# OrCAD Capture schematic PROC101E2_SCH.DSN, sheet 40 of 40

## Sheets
40 18. ICSSG RGMII_1 ETHERNET PHY: size C; title: ICSSG2 RGMII_1 ETHERNET PHY
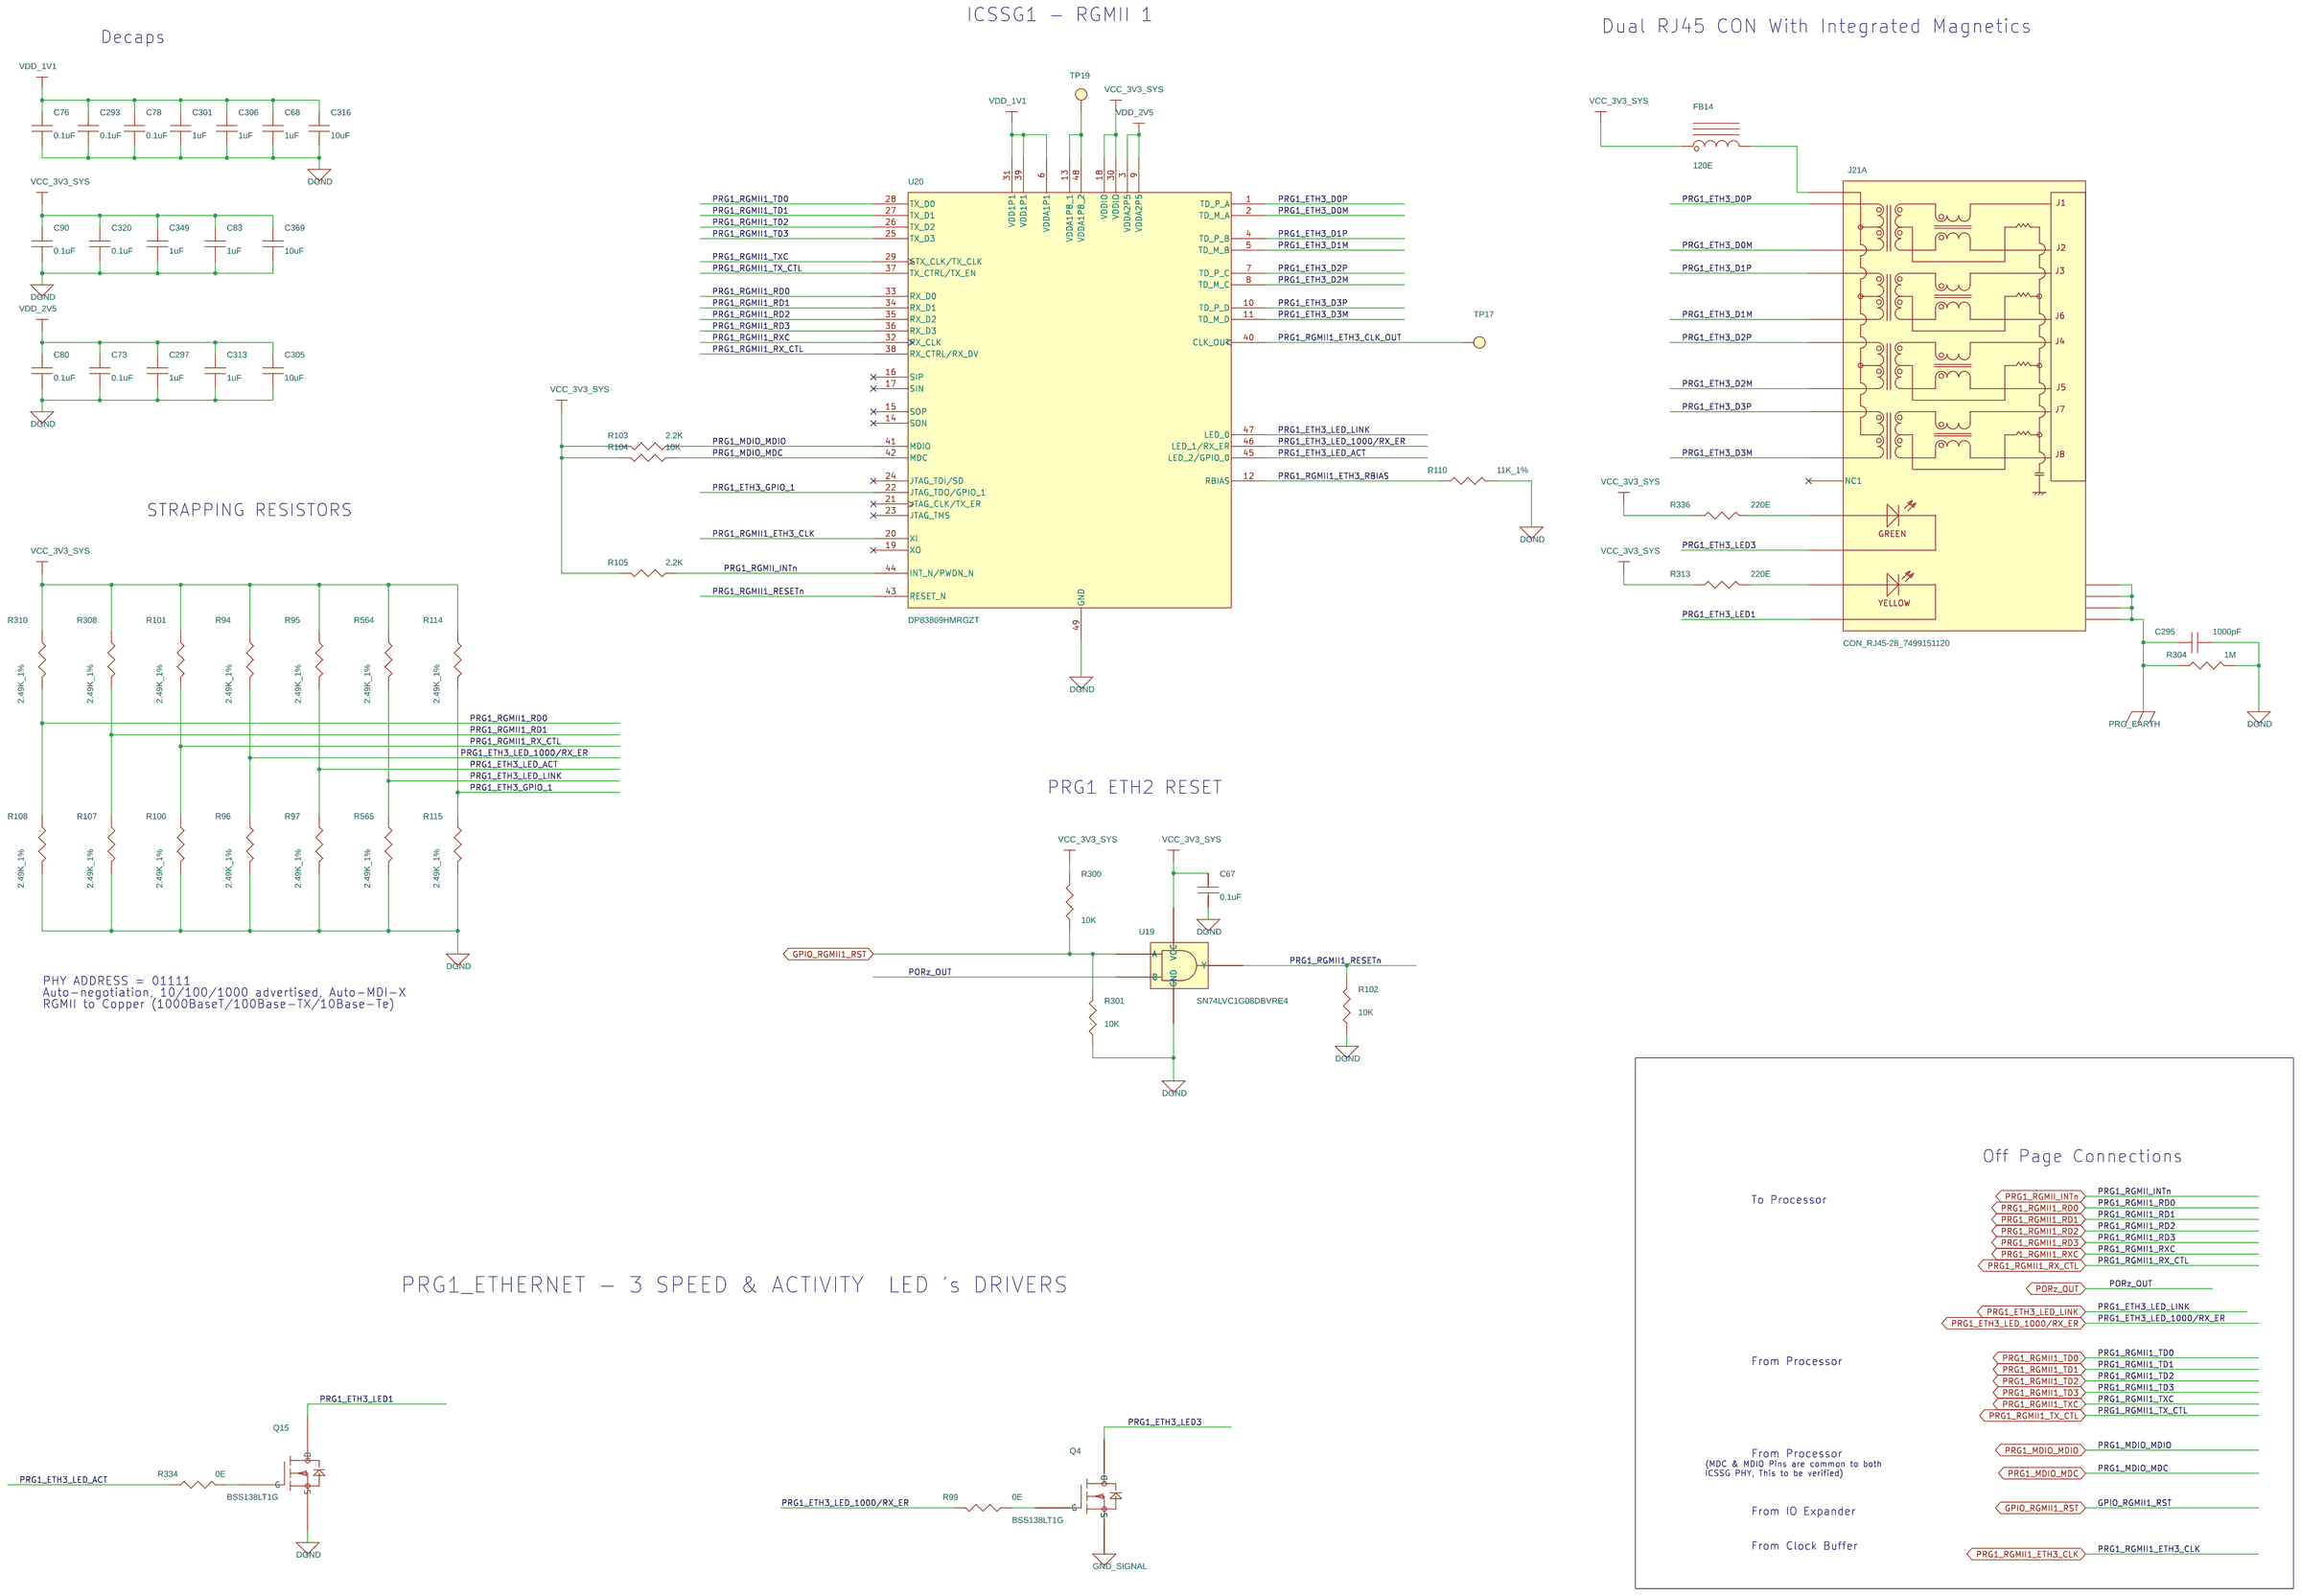
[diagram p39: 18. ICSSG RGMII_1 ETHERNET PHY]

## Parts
sheet 17. ICSSG RGMII_2 ETHERNET PHY
J21  CON_RJ45-28_7499151120  [CON_RJ45-28_7499151120_S_R_T_25-7]  (sections A,B)
sheet 18. ICSSG RGMII_1 ETHERNET PHY
C67  0.1uF  [CAP0402_0-75]
C68  1uF  [CAP0402_0-75]
C73  0.1uF  [CAP0402_0-75]
C76  0.1uF  [CAP0402_0-75]
C78  0.1uF  [CAP0402_0-75]
C80  0.1uF  [CAP0402_0-75]
C83  1uF  [CAP0402_0-75]
C90  0.1uF  [CAP0402_0-75]
C293  0.1uF  [CAP0402_0-75]
C295  1000pF  [CAP1206_1-75]
C297  1uF  [CAP0402_0-75]
C301  1uF  [CAP0402_0-75]
C305  10uF  [CAP0402_0-75]
C306  1uF  [CAP0402_0-75]
C313  1uF  [CAP0402_0-75]
C316  10uF  [CAP0402_0-75]
C320  0.1uF  [CAP0402_0-75]
C349  1uF  [CAP0402_0-75]
C369  10uF  [CAP0402_0-75]
FB14  120E  [IND0603_1]
Q4  BSS138LT1G  [SOT23-123_1-2]
Q15  BSS138LT1G  [SOT23-123_1-2]
R94  2.49K_1%  [RES0402_0-5]
R95  2.49K_1%  [RES0402_0-5]
R96  2.49K_1%  [RES0402_0-5]
R97  2.49K_1%  [RES0402_0-5]
R99  0E  [RES0402_0-5]
R100  2.49K_1%  [RES0402_0-5]
R101  2.49K_1%  [RES0402_0-5]
R102  10K  [RES0402_0-5]
R103  2.2K  [RES0402_0-5]
R104  10K  [RES0402_0-5]
R105  2.2K  [RES0402_0-5]
R107  2.49K_1%  [RES0402_0-5]
R108  2.49K_1%  [RES0402_0-5]
R110  11K_1%  [RES0402_0-5]
R114  2.49K_1%  [RES0402_0-5]
R115  2.49K_1%  [RES0402_0-5]
R300  10K  [RES0402_0-5]
R301  10K  [RES0402_0-5]
R304  1M  [RES0603_0-75]
R308  2.49K_1%  [RES0402_0-5]
R310  2.49K_1%  [RES0402_0-5]
R313  220E  [RES0402_0-5]
R334  0E  [RES0402_0-5]
R336  220E  [RES0402_0-5]
R564  2.49K_1%  [RES0402_0-5]
R565  2.49K_1%  [RES0402_0-5]
TP17  TP20_SMD  [TP20_SMD]
TP19  TP20_SMD  [TP20_SMD]
U19  SN74LVC1G08DBVRE4  [SOT23-5]
U20  DP83869HMRGZT  [QFN48_19-68_280X280_1_EP4-2]

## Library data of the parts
J21 = CON_RJ45-28_7499151120: CON JACK RJ45 STACKED 28POS FEMALE RT TH; Chkd/date: MANIRAJA/101118; Crtd /date: ALVY/091118; Custom_Duty: 24%; Customs_HS_Code: 85369090; Distributor_name: DIGIKEY; Distributor_part_number: 732-4961-5-ND; Footprint Path: Y:\MIS_DATABASE\Library\ALTIUM_TOOL\PCB_FOOTPRINTS\Altium_Footprint_Lib.PcbLib; Height: 25.63MM; Library Path: Y:\MIS_DATABASE\Library\ALTIUM_TOOL\SCHEMATICS_PARTS\MS_CONNECTOR_Library.schlib; Mfr_name: WURTH ELECTRONICS; Mfr_part_number: 7499151120; Mistral Part No: 150018110012-R; Package: THRU HOLE; Part_type: CONNECTOR\JACK; Project: NPOL_32SC; RoHS: RoHS; Temperature: -40°C+85°C; Tolerance: NA; Voltage: NA; Wattage: NA; Weight: NA; Datasheet: Y:\MIS_DATABASE\DATASHEETS\CONNECTORS\7499151120.PDF
C67 C73 C76 C78 C80 C90 C293 C320 = CAP: CAP CERAMIC 0.1uF 25V 20% X5R 0402; Alt_Mfr_name: YAGEO AMERICA; Alt_Mfr_part_number: CC0402KRX5R8BB104; Chkd/date: MANIRAJA/170820; Crtd /date: ALVY/170820; Custom_Duty: 15%; Customs_HS_Code: 85322990; Distributor_name: DIGIKEY; Distributor_part_number: 732-7495-1-ND; Footprint Path: Y:\MIS_DATABASE\Library\ALTIUM_TOOL\PCB_FOOTPRINTS\Altium_Footprint_Lib.PcbLib; Height: 0.55MM; Library Path: Y:\MIS_DATABASE\Library\ALTIUM_TOOL\SCHEMATICS_PARTS\MS_DISCRETE_Library.schlib; Mfr_name: WURTH ELECTRONICS; Mfr_part_number: 885012105018; Mistral Part No: 120020080003-R; Package: 0402; Part_type: CAPACITORS\CERAMIC; Project: AM64x_EVM_BRD; RoHS: RoHS; Temperature: -55°C+85°C; Tolerance: 20%; Voltage: 25V; Wattage: NA; Weight: 0.65mg; Datasheet: Y:\MIS_DATABASE\DATASHEETS\CAPACITORS\885012105018.PDF
C68 C83 C297 C301 C306 C313 C349 = CAP: CAP CERAMIC 1uF 10V 20% X5R 0402; Chkd/date: MANIRAJA/210820; Crtd /date: ALVY/190820; Custom_Duty: 15%; Customs_HS_Code: 85322990; Distributor_name: DIGIKEY; Distributor_part_number: 732-7489-1-ND; Footprint Path: Y:\MIS_DATABASE\Library\ALTIUM_TOOL\PCB_FOOTPRINTS\Altium_Footprint_Lib.PcbLib; Height: 0.55MM; Library Path: Y:\MIS_DATABASE\Library\ALTIUM_TOOL\SCHEMATICS_PARTS\MS_DISCRETE_Library.schlib; Mfr_name: WURTH ELECTRONICS; Mfr_part_number: 885012105012; Mistral Part No: 120020080009-R; Package: 0402; Part_type: CAPACITORS\CERAMIC; Project: AM64x_EVM_BRD; RoHS: RoHS; Temperature: -55°C+85°C; Tolerance: 20%; Voltage: 10V; Wattage: NA; Weight: 0.65mg; Datasheet: Y:\MIS_DATABASE\DATASHEETS\CAPACITORS\885012105012.PDF
C295 = CAP: CAP CERAMIC 1000pF 2KV 10% X7R 1206; Chkd/date: SHREESHAIL/291106; Crtd /date: MAZHAR/281106; Custom_Duty: 15%; Customs_HS_Code: 85322990; Distributor_name: DIGIKEY; Distributor_part_number: 478-2956-1-ND; Footprint Path: Y:\MIS_DATABASE\Library\ALTIUM_TOOL\PCB_FOOTPRINTS\Altium_Footprint_Lib.PcbLib; Height: 1.52MM; Library Path: Y:\MIS_DATABASE\Library\ALTIUM_TOOL\SCHEMATICS_PARTS\MS_DISCRETE_Library.schlib; Mfr_name: AVX CORPORATION; Mfr_part_number: 1206GC102KAT1A; Mistral Part No: 120015080006-R; Package: 1206; Part_type: CAPACITORS\CERAMIC; Project: ADR1B; RoHS: RoHS; Temperature: -55°C+125°C; Tolerance: 10%; Voltage: 2KV; Wattage: NA; Weight: 16.2mg; Datasheet: Y:\MIS_DATABASE\DATASHEETS\CAPACITORS\AVX_HV-MLC.PDF
C305 C316 C369 = CAP: CAP CERAMIC 10uF 10V 20% X5R 0402; Chkd/date: MANIRAJA/300520; Crtd /date: ALVY/260520; Custom_Duty: 15%; Customs_HS_Code: 85322990; Distributor_name: DIGIKEY; Distributor_part_number: 490-GRM155R61A106ME11DTR-ND; Footprint Path: Y:\MIS_DATABASE\Library\ALTIUM_TOOL\PCB_FOOTPRINTS\Altium_Footprint_Lib.PcbLib; Height: 0.55MM; Library Path: Y:\MIS_DATABASE\Library\ALTIUM_TOOL\SCHEMATICS_PARTS\MS_DISCRETE_Library.schlib; Mfr_name: MURATA; Mfr_part_number: GRM155R61A106ME11D; Mistral Part No: 120013110019-R; Package: 0402; Part_type: CAPACITORS\CERAMIC; Project: QCS610_NANOSOM; RoHS: RoHS; Temperature: -55°C+85°C; Tolerance: 20%; Voltage: 10V; Wattage: NA; Weight: 3.1mg; Datasheet: Y:\MIS_DATABASE\DATASHEETS\CAPACITORS\MURATA-GXX-SER_NOV17.PDF
FB14 = INDUCTOR_FERRITE: IND FERRITE BEAD CHIP 120E 2A 0603; Assembly: DNI; Chkd/date: MANIRAJA/180820; Crtd /date: ALVY/180820; Custom_Duty: 24%; Customs_HS_Code: 85437099; Distributor_name: DIGIKEY; Distributor_part_number: 732-782631141CT-ND; Footprint Path: Y:\MIS_DATABASE\Library\ALTIUM_TOOL\PCB_FOOTPRINTS\Altium_Footprint_Lib.PcbLib; Height: 1.00MM; Library Path: Y:\MIS_DATABASE\Library\ALTIUM_TOOL\SCHEMATICS_PARTS\MS_FILTER_Library.schlib; Mfr_name: WURTH ELECTRONICS; Mfr_part_number: 782631141; Mistral Part No: 130020080015-R; Package: 0603; Part_type: INDUCTOR; Project: AM64x_EVM_BRD; RoHS: RoHS; Temperature: -55°C+125°C; Tolerance: 25%; Voltage: NA; Wattage: NA; Weight: NA; Datasheet: Y:\MIS_DATABASE\DATASHEETS\DISCRETES\INDUCTORS\782631141.PDF
Q4 Q15 = MOSFET_BSS138LT1G: IC MOSFET N-CHANNEL 50V 200mA SOT23-3; Chkd/date: MANIRAJA/250219; Crtd /date: JEBRAN/060416; Custom_Duty: 15%; Customs_HS_Code: 85423100; Distributor_name: DIGIKEY; Distributor_part_number: BSS138LT1GOSCT-ND; Footprint Path: Y:\MIS_DATABASE\Library\ALTIUM_TOOL\PCB_FOOTPRINTS\Altium_Footprint_Lib.PcbLib; Height: 1.11MM; Library Path: Y:\MIS_DATABASE\Library\ALTIUM_TOOL\SCHEMATICS_PARTS\MS_MOSFET_Library.schlib; Library Ref: MOSFET_BSS138W; Mfr_name: ON SEMICONDUCTOR; Mistral Part No: 142016040001-R; Package: SOT23-3; Part_type: ICS\POWER\MOSFET; Project: LRDE_ABCM; RoHS: RoHS; Temperature: -55°C+150°C; Tolerance: NA; Voltage: NA; Wattage: NA; Weight: 8mg; Datasheet: Y:\MIS_DATABASE\DATASHEETS\DISCRETES\TRANSISTORS_FETS\BSS138LT1G.PDF
R94-R97 R100 R101 R107 R108 R114 R115 R564 = RESISTOR: RES 2.49K 1/16W 1% 0402; Assembly: DNI; Chkd/date: VASANTHA/270516; Crtd /date: VASANTHA/270516; Custom_Duty: 15%; Customs_HS_Code: 85332119; Distributor_name: DIGIKEY; Distributor_part_number: 311-2.49KLRCT-ND; Footprint Path: Y:\MIS_DATABASE\Library\ALTIUM_TOOL\PCB_FOOTPRINTS\Altium_Footprint_Lib.PcbLib; Height: 0.40MM; Library Path: Y:\MIS_DATABASE\Library\ALTIUM_TOOL\SCHEMATICS_PARTS\MS_DISCRETE_Library.schlib; Mfr_name: YAGEO AMERICA; Mfr_part_number: RC0402FR-072K49L; Mistral Part No: 110016050020-R; Package: 0402; Part_type: RESISTORS\FIXED; Project: TMDXCSKCC; RoHS: RoHS; Temperature: -55°C+155°C; Tolerance: 1%; Voltage: NA; Wattage: 1/16W; Weight: 0.65mg; Datasheet: Y:\MIS_DATABASE\DATASHEETS\RESISTORS\RCXXXXL-SER_MAR18.PDF
R99 R334 = RESISTOR: RES 0E 1/16W JUMPER 0402; Chkd/date: VASANTHA/201216; Crtd /date: MUDDU/190810; Custom_Duty: 15%; Customs_HS_Code: 85332119; Distributor_name: DIGIKEY; Distributor_part_number: 541-0.0JCT-ND; Footprint Path: Y:\MIS_DATABASE\Library\ALTIUM_TOOL\PCB_FOOTPRINTS\Altium_Footprint_Lib.PcbLib; Height: 0.40MM; Library Path: Y:\MIS_DATABASE\Library\ALTIUM_TOOL\SCHEMATICS_PARTS\MS_DISCRETE_Library.schlib; Mfr_name: VISHAY; Mfr_part_number: CRCW04020000Z0ED; Mistral Part No: 110010080019-R; Package: 0402; Part_type: RESISTORS\FIXED; Project: PB_BUGBASE; RoHS: RoHS; Temperature: -55°C+155°C; Tolerance: NA; Voltage: NA; Wattage: 1/16W; Weight: 0.65mg; Datasheet: Y:\MIS_DATABASE\DATASHEETS\RESISTORS\CRCW0603.PDF
R102 R104 R301 = RESISTOR: RES 10K 1/16W 5% 0402; Assembly: DNI; Chkd/date: VASANTHA/061216; Crtd /date: MAZHAR/230805; Custom_Duty: 15%; Customs_HS_Code: 85332119; Distributor_name: DIGIKEY; Distributor_part_number: 311-10KJRCT-ND; Footprint Path: Y:\MIS_DATABASE\Library\ALTIUM_TOOL\PCB_FOOTPRINTS\Altium_Footprint_Lib.PcbLib; Height: 0.40MM; Library Path: Y:\MIS_DATABASE\Library\ALTIUM_TOOL\SCHEMATICS_PARTS\MS_DISCRETE_Library.schlib; Mfr_name: YAGEO AMERICA; Mfr_part_number: RC0402JR-0710KL; Mistral Part No: 110011060021-R; Package: 0402; Part_type: RESISTORS\FIXED; Project: HSE; RoHS: RoHS; Temperature: -55°C+155°C; Tolerance: 5%; Voltage: NA; Wattage: 1/16W; Weight: 0.65mg; Datasheet: Y:\MIS_DATABASE\DATASHEETS\RESISTORS\RCXXXXL-SER_MAR18.PDF
R103 R105 = RESISTOR: RES 2.2K 1/16W 5% 0402; Chkd/date: VASANTHA/061216; Crtd /date: BAVISH/021210; Custom_Duty: 15%; Customs_HS_Code: 85332119; Distributor_name: DIGIKEY; Distributor_part_number: 311-2.2KJRCT-ND; Footprint Path: Y:\MIS_DATABASE\Library\ALTIUM_TOOL\PCB_FOOTPRINTS\Altium_Footprint_Lib.PcbLib; Height: 0.40MM; Library Path: Y:\MIS_DATABASE\Library\ALTIUM_TOOL\SCHEMATICS_PARTS\MS_DISCRETE_Library.schlib; Mfr_name: YAGEO AMERICA; Mfr_part_number: RC0402JR-072K2L; Mistral Part No: 110010120018-R; Package: 0402; Part_type: RESISTORS\FIXED; Project: TE4; RoHS: RoHS; Temperature: -55°C+155°C; Tolerance: 5%; Voltage: NA; Wattage: 1/16W; Weight: 0.65mg; Datasheet: Y:\MIS_DATABASE\DATASHEETS\RESISTORS\RCXXXXL-SER_MAR18.PDF
R110 = RESISTOR: RES 11K 1/16W 1% 0402; Chkd/date: VASANTHA/251115; Crtd /date: VASANTHA/251115; Custom_Duty: 15%; Customs_HS_Code: 85332119; Distributor_name: DIGIKEY; Distributor_part_number: 311-11.0KLRCT-ND; Footprint Path: Y:\MIS_DATABASE\Library\ALTIUM_TOOL\PCB_FOOTPRINTS\Altium_Footprint_Lib.PcbLib; Height: 0.40MM; Library Path: Y:\MIS_DATABASE\Library\ALTIUM_TOOL\SCHEMATICS_PARTS\MS_DISCRETE_Library.schlib; Mfr_name: YAGEO AMERICA; Mfr_part_number: RC0402FR-0711KL; Mistral Part No: 110015110012-R; Package: 0402; Part_type: RESISTORS\FIXED; Project: TI_VLAN_SWITCH; RoHS: RoHS; Temperature: -55°C+155°C; Tolerance: 1%; Voltage: NA; Wattage: 1/16W; Weight: 0.65mg; Datasheet: Y:\MIS_DATABASE\DATASHEETS\RESISTORS\RCXXXXL-SER_MAR18.PDF
R300 = RESISTOR: RES 10K 1/16W 5% 0402; Chkd/date: VASANTHA/061216; Crtd /date: MAZHAR/230805; Custom_Duty: 15%; Customs_HS_Code: 85332119; Distributor_name: DIGIKEY; Distributor_part_number: 311-10KJRCT-ND; Footprint Path: Y:\MIS_DATABASE\Library\ALTIUM_TOOL\PCB_FOOTPRINTS\Altium_Footprint_Lib.PcbLib; Height: 0.40MM; Library Path: Y:\MIS_DATABASE\Library\ALTIUM_TOOL\SCHEMATICS_PARTS\MS_DISCRETE_Library.schlib; Mfr_name: YAGEO AMERICA; Mfr_part_number: RC0402JR-0710KL; Mistral Part No: 110011060021-R; Package: 0402; Part_type: RESISTORS\FIXED; Project: HSE; RoHS: RoHS; Temperature: -55°C+155°C; Tolerance: 5%; Voltage: NA; Wattage: 1/16W; Weight: 0.65mg; Datasheet: Y:\MIS_DATABASE\DATASHEETS\RESISTORS\RCXXXXL-SER_MAR18.PDF
R304 = RESISTOR: RES 1M 1/10W 5% 0603; Chkd/date: VASANTHA/060217; Crtd /date: USMAN/111207; Custom_Duty: 15%; Customs_HS_Code: 85332119; Distributor_name: DIGIKEY; Distributor_part_number: P1.0MGCT-ND; Footprint Path: Y:\MIS_DATABASE\Library\ALTIUM_TOOL\PCB_FOOTPRINTS\Altium_Footprint_Lib.PcbLib; Height: 0.55MM; Library Path: Y:\MIS_DATABASE\Library\ALTIUM_TOOL\SCHEMATICS_PARTS\MS_DISCRETE_Library.schlib; Mfr_name: PANASONIC-ECG; Mfr_part_number: ERJ-3GEYJ105V; Mistral Part No: 110009030413-R; Package: 0603; Part_type: RESISTORS\FIXED; Project: BSN; RoHS: RoHS; Temperature: -55°C+155°C; Tolerance: 5%; Voltage: NA; Wattage: 1/10W; Weight: 2mg; Datasheet: Y:\MIS_DATABASE\DATASHEETS\RESISTORS\PAN-ERJSER_NOV17.PDF
R308 R310 R565 = RESISTOR: RES 2.49K 1/16W 1% 0402; Chkd/date: VASANTHA/270516; Crtd /date: VASANTHA/270516; Custom_Duty: 15%; Customs_HS_Code: 85332119; Distributor_name: DIGIKEY; Distributor_part_number: 311-2.49KLRCT-ND; Footprint Path: Y:\MIS_DATABASE\Library\ALTIUM_TOOL\PCB_FOOTPRINTS\Altium_Footprint_Lib.PcbLib; Height: 0.40MM; Library Path: Y:\MIS_DATABASE\Library\ALTIUM_TOOL\SCHEMATICS_PARTS\MS_DISCRETE_Library.schlib; Mfr_name: YAGEO AMERICA; Mfr_part_number: RC0402FR-072K49L; Mistral Part No: 110016050020-R; Package: 0402; Part_type: RESISTORS\FIXED; Project: TMDXCSKCC; RoHS: RoHS; Temperature: -55°C+155°C; Tolerance: 1%; Voltage: NA; Wattage: 1/16W; Weight: 0.65mg; Datasheet: Y:\MIS_DATABASE\DATASHEETS\RESISTORS\RCXXXXL-SER_MAR18.PDF
R313 R336 = RESISTOR: RES 220E 1/10W 5% 0402; Chkd/date: VASANTHA/291216; Crtd /date: GEETHA/260406; Custom_Duty: 15%; Customs_HS_Code: 85332119; Distributor_name: DIGIKEY; Distributor_part_number: P220JCT-ND; Footprint Path: Y:\MIS_DATABASE\Library\ALTIUM_TOOL\PCB_FOOTPRINTS\Altium_Footprint_Lib.PcbLib; Height: 0.40MM; Library Path: Y:\MIS_DATABASE\Library\ALTIUM_TOOL\SCHEMATICS_PARTS\MS_DISCRETE_Library.schlib; Mfr_name: PANASONIC-ECG; Mfr_part_number: ERJ-2GEJ221X; Mistral Part No: 110009030506-R; Package: 0402; Part_type: RESISTORS\FIXED; Project: RED EYE; RoHS: RoHS; Temperature: -55°C+155°C; Tolerance: 5%; Voltage: NA; Wattage: 1/10W; Weight: 0.8mg; Datasheet: Y:\MIS_DATABASE\DATASHEETS\RESISTORS\PAN-ERJSER_NOV17.PDF
TP17 TP19 = TESTPOINT: TESTPOINT CIR 20 SMD; Chkd/date: SHREESHAIL/171006; Crtd /date: MAZHAR/171006; Custom_Duty: NA; Customs_HS_Code: NA; Distributor_name: NA; Distributor_part_number: NA; Footprint Path: Y:\MIS_DATABASE\Library\ALTIUM_TOOL\PCB_FOOTPRINTS\Altium_Footprint_Lib.PcbLib; Height: NA; Library Path: Y:\MIS_DATABASE\Library\ALTIUM_TOOL\SCHEMATICS_PARTS\MS_DISCRETE_Library.schlib; MECHANICAL 3D STEP FILE: NA; Mfr_name: LOCAL; Mistral Part No: NA; Package: SMD; Project: BT MODULE_CSRBC04; RoHS: NA; Temperature: NA; Tolerance: NA; Voltage: NA; Wattage: NA; Weight: NA; Datasheet: NA
U19 = SN74LVC1G08DBVRE4_SOT23-5: IC SINGLE 2-INPUT POSITIVE AND GATE SOT23-5; Chkd/date: SUHAS/221010; Crtd /date: USMAN/151008; Custom_Duty: 15%; Customs_HS_Code: 85423100; Distributor_name: DIGIKEY; Distributor_part_number: SN74LVC1G08DBVRE4-ND; Height: 1.45MM; Mfr_name: TEXAS INSTRUMENTS; Mistral Part No: 141009060026-R; Part_type: ICS\DIGITAL\GATES; Project: KHAN_MAIN; RoHS: Sb/ Br FREE; Temperature: -40°C+85°C; Datasheet: Y:\MIS_DATABASE\DATASHEETS\ICS\DIGITAL\GATES\SN74LVC1G08.PDF
U20 = DP83869HM_VQFN48: IC ETHERNET TRANSCEIVER 10/100/1000 WITH COPPER AND FIBRE INTERFACE VQFN48; Chkd/date: MANIRAJA/060519; Crtd /date: ALVY/060519; Custom_Duty: 15%; Customs_HS_Code: 85423100; Distributor_name: DIGIKEY; Distributor_part_number: 296-53377-1-ND; Footprint Path: Y:\MIS_DATABASE\Library\ALTIUM_TOOL\PCB_FOOTPRINTS\Altium_Footprint_Lib.PcbLib; Height: 1.00MM; Library Path: Y:\MIS_DATABASE\Library\ALTIUM_TOOL\SCHEMATICS_PARTS\MS_TELECOM_Library.schlib; Mfr_name: TEXAS INSTRUMENTS; Mistral Part No: 143019050002-R; Package: VQFN48; Part_type: ICS\TELECOM\TRANSCEIVER; Project: J7ES_ENET_DP83869HM_EXP; RoHS: RoHS; Temperature: -40°C+125°C; Tolerance: NA; Voltage: NA; Wattage: NA; Weight: NA; Datasheet: Y:\MIS_DATABASE\DATASHEETS\ICS\TELECOM\DP83869HM.PDF

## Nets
DGND: C67.2 C68.2 C73.2 C76.2 C78.2 C80.2 C83.2 C90.2 C293.2 C295.2 C297.2 C301.2 C305.2 C306.2 C313.2 C316.2 C320.2 C349.2 C369.2 Q4.2(S) Q15.2(S) R96.2 R97.2 R100.2 R102.2 R107.2 R108.2 R110.1 R115.2 R301.2 R304.2 R565.2 U19.3(GND) U20.49(GND) ; also on sheet 2 3 4 5 6 7 8 9 10 11 12 13 14 15 16 17 18 19 20 21 22 23 24 25 26 27 28 29 30 39
VCC_3V3_SYS: C67.1 C83.1 C90.1 C320.1 C349.1 C369.1 FB14.1 R94.1 R95.1 R101.1 R103.2 R104.1 R105.2 R114.1 R300.2 R308.1 R310.1 R313.1 R336.1 R564.1 U19.5(VCC) U20.18(VDDIO) U20.30(VDDIO) ; also on sheet 2 5 6 7 8 10 11 12 13 14 15 16 17 18 19 20 21 23 24 25 26 27 29 30 39
VDD_1V1: C68.1 C76.1 C78.1 C293.1 C301.1 C306.1 C316.1 U20.6(VDDA1P1) U20.31(VDD1P1) U20.39(VDD1P1) ; also on sheet 16 39
VDD_2V5: C73.1 C80.1 C297.1 C305.1 C313.1 U20.3(VDDA2P5) U20.9(VDDA2P5) ; also on sheet 2 16 39
GPIO_RGMII1_RST: R300.1 R301.1 U19.1(A) ; also on sheet 13
PORz_OUT: U19.2(B) ; also on sheet 2 12 24 29 39
PRG1_ETH3_D0M: J21.A3 U20.2(TD_M_A)
PRG1_ETH3_D0P: J21.A2 U20.1(TD_P_A)
PRG1_ETH3_D1M: J21.A7 U20.5(TD_M_B)
PRG1_ETH3_D1P: J21.A4 U20.4(TD_P_B)
PRG1_ETH3_D2M: J21.A6 U20.8(TD_M_C)
PRG1_ETH3_D2P: J21.A5 U20.7(TD_P_C)
PRG1_ETH3_D3M: J21.A9 U20.11(TD_M_D)
PRG1_ETH3_D3P: J21.A8 U20.10(TD_P_D)
PRG1_ETH3_GPIO_1: R114.2 R115.1 U20.22(JTAG_TDO/GPIO_1)
PRG1_ETH3_LED1: J21.A13 Q15.3(D)
PRG1_ETH3_LED3: J21.A12 Q4.3(D)
PRG1_ETH3_LED_1000/RX_ER: R94.2 R96.1 R99.2 U20.46(LED_1/RX_ER) ; also on sheet 18
PRG1_ETH3_LED_ACT: R95.2 R97.1 R334.1 U20.45(LED_2/GPIO_0)
PRG1_ETH3_LED_LINK: R564.2 R565.1 U20.47(LED_0) ; also on sheet 18
PRG1_MDIO_MDC: R104.2 U20.42(MDC) ; also on sheet 18 39
PRG1_MDIO_MDIO: R103.1 U20.41(MDIO) ; also on sheet 18 39
PRG1_RGMII1_ETH3_CLK: U20.20(XI) ; also on sheet 11
PRG1_RGMII1_ETH3_CLK_OUT: TP17.1(TP) U20.40(CLK_OUT)
PRG1_RGMII1_ETH3_RBIAS: R110.2 U20.12(RBIAS)
PRG1_RGMII1_RD0: R108.1 R310.2 U20.33(RX_D0) ; also on sheet 18
PRG1_RGMII1_RD1: R107.1 R308.2 U20.34(RX_D1) ; also on sheet 18
PRG1_RGMII1_RD2: U20.35(RX_D2) ; also on sheet 18
PRG1_RGMII1_RD3: U20.36(RX_D3) ; also on sheet 18
PRG1_RGMII1_RESETn: R102.1 U19.4(Y) U20.43(RESET_N)
PRG1_RGMII1_RX_CTL: R100.1 R101.2 U20.38(RX_CTRL/RX_DV) ; also on sheet 18
PRG1_RGMII1_RXC: U20.32(RX_CLK) ; also on sheet 18
PRG1_RGMII1_TD0: U20.28(TX_D0) ; also on sheet 18
PRG1_RGMII1_TD1: U20.27(TX_D1) ; also on sheet 18
PRG1_RGMII1_TD2: U20.26(TX_D2) ; also on sheet 18
PRG1_RGMII1_TD3: U20.25(TX_D3) ; also on sheet 18
PRG1_RGMII1_TX_CTL: U20.37(TX_CTRL/TX_EN) ; also on sheet 18
PRG1_RGMII1_TXC: U20.29(GTX_CLK/TX_CLK) ; also on sheet 18
PRG1_RGMII_INTn: R105.1 U20.44(INT_N/PWDN_N) ; also on sheet 2 12 39
PRG_EARTH: C295.1 J21.SH1 J21.SH2 J21.SH3 J21.SH4 R304.1
N24775601: TP19.1(TP) U20.13(VDDA1P8_1) U20.48(VDDA1P8_2)
N24776171: Q15.1(G) R334.2
N24776230: Q4.1(G) R99.1
N27219244: FB14.2 J21.A1
N27219534: J21.A14 R313.2
N27219552: J21.A11 R336.2

Not connected (* = marked no-connect by the designer): J21 A10(NC1)*; U20 14(SON)* 15(SOP)* 16(SIP)* 17(SIN)* 19(XO)* 21(JTAG_CLK/TX_ER)* 23(JTAG_TMS)* 24(JTAG_TDI/SD)*

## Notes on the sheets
sheet 40
- ICSSG1 - RGMII 1
- Dual RJ45 CON With Integrated Magnetics
- Decaps
- STRAPPING RESISTORS
- PRG1 ETH2 RESET
- PHY ADDRESS = 01111
- Auto-negotiation, 10/100/1000 advertised, Auto-MDI-X
- RGMII to Copper (1000BaseT/100Base-TX/10Base-Te)
- Off Page Connections
- To Processor
- PRG1_ETHERNET - 3 SPEED & ACTIVITY  LED 's DRIVERS
- From Processor
- From Processor
- (MDC & MDIO Pins are common to both
  ICSSG PHY, This to be verified)
- From IO Expander
- From Clock Buffer
